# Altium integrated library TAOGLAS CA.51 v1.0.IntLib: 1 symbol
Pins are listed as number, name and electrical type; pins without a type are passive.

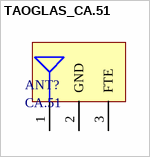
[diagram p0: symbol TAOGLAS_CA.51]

## TAOGLAS_CA.51
designator ANT?, comment CA.51
5.9GHz C-V2X Ceramic SMD Mount Chip Antenna / 5850MHz to 5925MHz; ComponentLibStatus: Created; Temp_Low: -40C; MFG: Taoglas; Temp_High: +85C
footprint TAOGLAS_CA.51 (5.9GHz C-V2X Ceramic SMD Mount Chip Antenna  5850MHz to 5925MHz)
pins: 1 RF OUT, 2 GND, 3 FTE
